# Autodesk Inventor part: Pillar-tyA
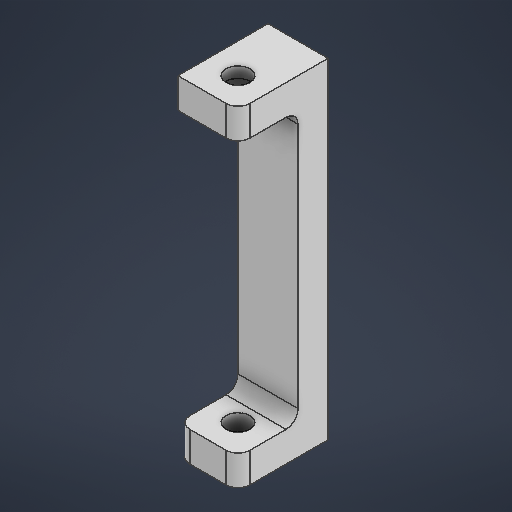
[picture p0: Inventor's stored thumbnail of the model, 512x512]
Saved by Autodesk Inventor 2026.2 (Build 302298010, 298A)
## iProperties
Created: 2026-05
Part Number: Pillar-tyA
Material: 일반
Document SubType Name: Modeling
Designer: work
Density: 1 g/cm^3
Appearance: 기본값
Author: work
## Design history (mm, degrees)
sketch "스케치1"
  geometry: L1 (-5, 5)-(5, 5); L2 (5, 5)-(5, -5); L3 (5, -5)-(-5, -5); L4 (-5, -5)-(-5, 5); L5 (-5, 5)-(5, -5); L6 (5, 5)-(-5, -5); L7 (5, -5)-(-5, -5); L8 (-5, -5)-(-5, -11); L9 (-5, -11)-(5, -11); L10 (5, -11)-(5, -5); C1 r 2 at (0, 0); C2 r 3.1 at (4, 4); 3 further points
  constraints: 20 end point, 4 parallel, 2 centre point, 2 horizontal, 2 midpoint, 2 perpendicular, 1 coincident
  dimensions: "d0" = 4 diameter of C1; "d1" = 10 distance of L2.end L3.end; "d2" = 10 distance of L1.end L2.end; "d3" = 6 distance of L9.end L2.end; "d4" = 6.2 diameter of C2; "d5" = 4 horizontal distance of point (0, 0) C2.centre; "d6" = 4 horizontal distance of C2.centre point (0, 0)
extrude "돌출1" new body sketch "스케치1" distance "d7" = 5; taper "d8" = 0 deg
extrude "돌출2" join sketch "스케치1" distance "d9" = 50; taper "d10" = 0 deg
sketch "스케치2"
  geometry: L1 (5, 5)-(-5, 5) reference; L2 (-5, 5)-(-5, -5) reference; L3 (-5, -5)-(5, -5) reference; L4 (5, -5)-(5, 5) reference; L5 (-5, 5)-(5, 5) reference; L6 (5, 5)-(5, 11) reference; L7 (5, 11)-(-5, 11) reference; L8 (-5, 11)-(-5, 5) reference; L9 (-5, -1.066)-(-5, -5); L10 (-5, -5)-(-1.066, -5); C1 r 2 at (0, 0) reference; 5 further points
  constraints: 4 end point, 1 perpendicular, 1 vertical
extrude "돌출3" join sketch "스케치2" distance "d11" = 5; taper "d12" = 0 deg
sketch "스케치3"
  geometry: C1 r 2 at (0, 0) reference; 2 further points
  constraints: 1 coincident
hole "구멍1" sketch "스케치3" at (0, 0) diameter "d13" = 4; stored, may be unused: countersink angle "d17" = 90 deg, drill point angle "d19" = 118 deg; dims "d14" = 6, "d15" = 6.2, "d16" = 3.2, "d18" = 8
fillet "모깎기1" dims "d20" = 2
chamfer "모따기1" distance "d21" = 1; stored, may be unused: second distance "d22" = 2, angle "d23" = 45 deg
node "솔리드1"
node "투영된 루프1"
node "투영된 루프2"
feature "A9D066F2-1C7D-4E18-AEED-F7BC21143FA4" dims "d13" = 4, "d14" = 6, "d15" = 6.2, "d16" = 3.2, "d17" = 90 deg, "d18" = 8, "d19" = 118 deg
